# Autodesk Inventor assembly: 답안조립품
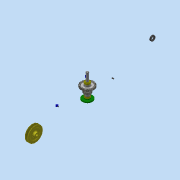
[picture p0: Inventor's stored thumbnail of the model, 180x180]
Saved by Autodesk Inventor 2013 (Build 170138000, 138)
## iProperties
Created: 2017-11
Part Number: 답안조립품
Document SubType Name: Assembly
Designer: Administrator
Author: Administrator
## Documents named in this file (14)
- C:\Users\Administrator\Desktop\471108V1023\답안조립품.iam
- C:\Users\Administrator\Desktop\471108V1023\V-벨트풀리.ipt
- C:\Users\Administrator\Desktop\471108V1023\뒤커버.ipt
- C:\Users\Administrator\Desktop\471108V1023\멈춤나사 - M4 x 10.ipt
- 멈춤나사 - M4 x 10.ipt
- C:\Users\Administrator\Desktop\471108V1023\베어링 6002.ipt
- C:\Users\Administrator\Desktop\471108V1023\본체.ipt
- C:\Users\Administrator\Desktop\471108V1023\볼트 M3 x 8.ipt
- C:\Users\Administrator\Desktop\471108V1023\스퍼기어.ipt
- C:\Users\Administrator\Desktop\471108V1023\앞커버.ipt
- C:\Users\Administrator\Desktop\471108V1023\오일 실 15 30 7.ipt
- C:\Users\Administrator\Desktop\471108V1023\축.ipt
- C:\Users\Administrator\Desktop\471108V1023\키 - 5 x 5 x 18.ipt
- C:\Users\Administrator\Desktop\471108V1023\키 - 6 x 6 x 22.ipt
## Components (1 placed, 1 different names)
1. V-벨트풀리:1
